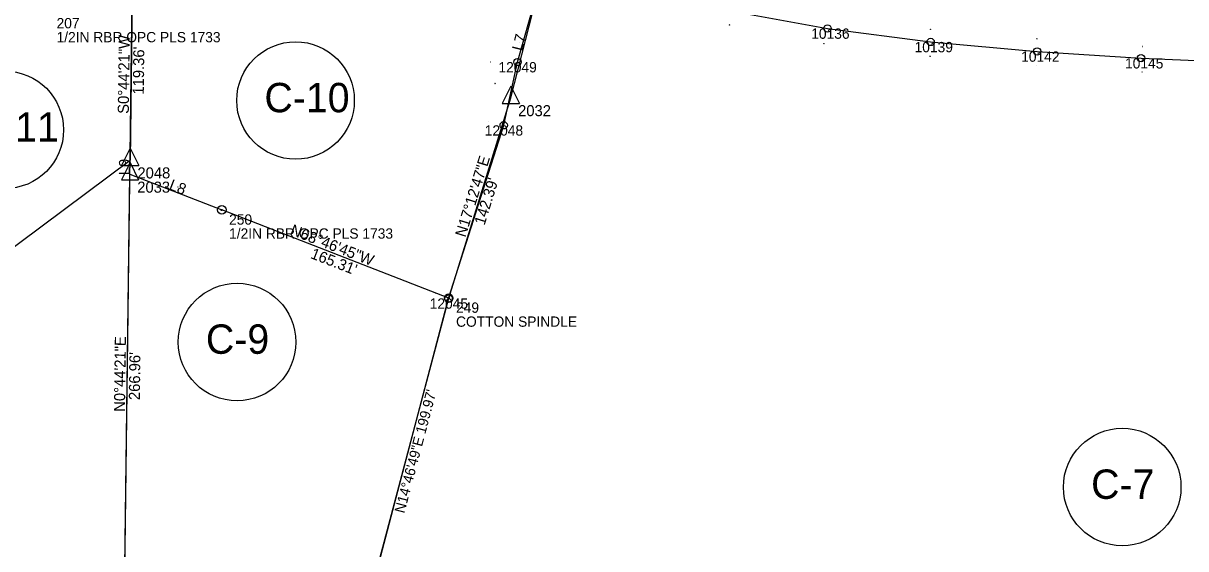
# Model space of a CAD drawing. Extents: x 1431802 to 1457777, y 1852108 to 1876350.
# Drawn here: x 1443655 to 1444444, y 1854558 to 1854914 of the extents above; entities that cross this region are included whole.
import ezdxf

# ---------------------------------------------------------------- set-up
doc = ezdxf.new("R2010")
doc.units = 0
for name, color, linetype in [('Default', 7, 'Continuous'), ('S_CAL_CORNER', 7, 'Continuous'), ('S_CAL_CORNER_ANNOT', 7, 'Continuous'), ('S_EXISTING_ALIGNMENT', 7, 'Continuous'), ('S_EXISTING_ALIGNMENT_ANNOT', 7, 'Continuous'), ('S_IRON_PIN', 7, 'Continuous'), ('S_IRON_PIN_ANNOT', 7, 'Continuous'), ('S_PROPERTY', 7, 'Continuous'), ('S_PROPERTY_ANNOT', 7, 'Continuous'), ('S_RDW_PT_SYM', 7, 'Continuous'), ('S_SECTION', 7, 'Continuous')]:
    doc.layers.add(name, color=color, linetype=linetype)

msp = doc.modelspace()

# ---------------------------------------------------------------- linework, layer by layer
at = {"layer": 'Default'}
for points in [[(1443991.62, 1854901.34), (1443991.57, 1854901.35), (1443991.62, 1854901.34), (1443991.61, 1854901.29), (1443991.62, 1854901.34), (1443991.67, 1854901.33), (1443991.62, 1854901.34), (1443991.63, 1854901.39)], [(1443723.6, 1854816.71), (1443723.55, 1854816.71), (1443723.6, 1854816.71), (1443723.6, 1854816.66), (1443723.6, 1854816.71), (1443723.65, 1854816.71), (1443723.6, 1854816.71), (1443723.6, 1854816.76)], [(1443759.83, 1854803.21), (1443759.85, 1854803.26), (1443759.83, 1854803.21), (1443759.78, 1854803.23), (1443759.83, 1854803.21), (1443759.81, 1854803.16), (1443759.83, 1854803.21), (1443759.88, 1854803.19)]]:
    msp.add_lwpolyline(points, dxfattribs=at)
at = {"layer": 'S_CAL_CORNER'}
for p, q in [((1443985.99, 1854871.76), (1443980.11, 1854859.94)), ((1443985.99, 1854871.76), (1443991.8, 1854859.94)), ((1443980.11, 1854859.94), (1443991.8, 1854859.94)), ((1443727.5, 1854829.48), (1443721.62, 1854817.67)), ((1443727.5, 1854829.48), (1443733.31, 1854817.67)), ((1443727.38, 1854819.8), (1443721.5, 1854807.99)), ((1443721.62, 1854817.67), (1443733.31, 1854817.67)), ((1443727.38, 1854819.8), (1443733.19, 1854807.99)), ((1443721.5, 1854807.99), (1443733.19, 1854807.99))]:
    msp.add_line(p, q, dxfattribs=at)
at = {"layer": 'S_EXISTING_ALIGNMENT'}
for p, q in [((1443990.44, 1854888.01), (1444004.54, 1854937.19)), ((1444136.32, 1854922.52), (1444201, 1854910.83)), ((1444201, 1854910.83), (1444271.02, 1854901.68)), ((1444271.02, 1854901.68), (1444343.36, 1854895.24)), ((1444343.36, 1854895.24), (1444413.89, 1854890.65)), ((1443981.13, 1854845.08), (1443990.44, 1854888.01)), ((1444413.89, 1854890.65), (1444489.02, 1854887.49)), ((1443943.72, 1854727.53), (1443981.13, 1854845.08)), ((1443892.71, 1854534.17), (1443943.72, 1854727.53))]:
    msp.add_line(p, q, dxfattribs=at)
for centre in [(1444201, 1854910.83), (1444271.02, 1854901.68), (1444343.36, 1854895.24), (1443990.44, 1854888.01), (1444413.89, 1854890.65), (1443981.13, 1854845.08), (1443943.72, 1854727.53)]:
    msp.add_circle(centre, 2.5, dxfattribs=at)
at = {"layer": 'S_IRON_PIN'}
for centre, radius in [((1443789.66, 1854787.6), 2.91), ((1443789.66, 1854787.6), 0.411), ((1443789.66, 1854787.6), 0.262), ((1443789.66, 1854787.6), 0.212), ((1443789.66, 1854787.6), 0.145), ((1443789.66, 1854787.6), 0.0822), ((1443789.66, 1854787.6), 0.0581), ((1443943.76, 1854727.77), 2.91), ((1443943.76, 1854727.77), 0.411), ((1443943.76, 1854727.77), 0.262), ((1443943.76, 1854727.77), 0.212), ((1443943.76, 1854727.77), 0.145), ((1443943.76, 1854727.77), 0.0822), ((1443943.76, 1854727.77), 0.0581)]:
    msp.add_circle(centre, radius, dxfattribs=at)
at = {"layer": 'S_PROPERTY'}
for p, q in [((1443728.95, 1854940.85), (1443727.41, 1854821.5)), ((1443985.9, 1854863.78), (1444004.6, 1854937.04)), ((1443943.76, 1854727.77), (1443985.9, 1854863.78)), ((1443347.68, 1854538.17), (1443727.41, 1854821.5)), ((1443727.29, 1854811.82), (1443727.41, 1854821.5)), ((1443723.84, 1854544.89), (1443727.29, 1854811.82)), ((1443727.29, 1854811.82), (1443789.66, 1854787.6)), ((1443943.76, 1854727.77), (1443789.66, 1854787.6)), ((1443789.66, 1854144.76), (1443943.76, 1854727.77))]:
    msp.add_line(p, q, dxfattribs=at)
for centre in [(1443839.79, 1854861.92), (1443642.38, 1854841.97), (1443800.04, 1854697.92), (1444401.12, 1854599.42)]:
    msp.add_circle(centre, 39.9, dxfattribs=at)
at = {"layer": 'S_RDW_PT_SYM'}
for points in [[(1444134.38, 1854913.21), (1444134.38, 1854913.26), (1444134.38, 1854913.21), (1444134.33, 1854913.21), (1444134.38, 1854913.21), (1444134.38, 1854913.16), (1444134.38, 1854913.21), (1444134.43, 1854913.21)], [(1444271.03, 1854910.26), (1444271.03, 1854910.31), (1444271.03, 1854910.26), (1444270.98, 1854910.26), (1444271.03, 1854910.26), (1444271.03, 1854910.21), (1444271.03, 1854910.26), (1444271.08, 1854910.26)], [(1444343.21, 1854903.87), (1444343.21, 1854903.92), (1444343.21, 1854903.87), (1444343.16, 1854903.87), (1444343.21, 1854903.87), (1444343.21, 1854903.82), (1444343.21, 1854903.87), (1444343.26, 1854903.87)], [(1444198.59, 1854900.72), (1444198.59, 1854900.77), (1444198.59, 1854900.72), (1444198.54, 1854900.72), (1444198.59, 1854900.72), (1444198.59, 1854900.67), (1444198.59, 1854900.72), (1444198.65, 1854900.72)], [(1444414.8, 1854898.63), (1444414.8, 1854898.68), (1444414.8, 1854898.63), (1444414.75, 1854898.63), (1444414.8, 1854898.63), (1444414.8, 1854898.58), (1444414.8, 1854898.63), (1444414.85, 1854898.63)], [(1443972.27, 1854888.19), (1443972.27, 1854888.24), (1443972.27, 1854888.19), (1443972.22, 1854888.19), (1443972.27, 1854888.19), (1443972.27, 1854888.14), (1443972.27, 1854888.19), (1443972.32, 1854888.19)], [(1444270.63, 1854891.92), (1444270.63, 1854891.97), (1444270.63, 1854891.92), (1444270.58, 1854891.92), (1444270.63, 1854891.92), (1444270.63, 1854891.87), (1444270.63, 1854891.92), (1444270.68, 1854891.92)], [(1444342.88, 1854885.9), (1444342.88, 1854885.95), (1444342.88, 1854885.9), (1444342.83, 1854885.9), (1444342.88, 1854885.9), (1444342.88, 1854885.85), (1444342.88, 1854885.9), (1444342.93, 1854885.9)], [(1444002.36, 1854885.42), (1444002.36, 1854885.47), (1444002.36, 1854885.42), (1444002.31, 1854885.42), (1444002.36, 1854885.42), (1444002.36, 1854885.37), (1444002.36, 1854885.42), (1444002.41, 1854885.42)], [(1444414.63, 1854881.32), (1444414.63, 1854881.37), (1444414.63, 1854881.32), (1444414.58, 1854881.32), (1444414.63, 1854881.32), (1444414.63, 1854881.27), (1444414.63, 1854881.32), (1444414.68, 1854881.32)], [(1443975.24, 1854873.57), (1443975.24, 1854873.62), (1443975.24, 1854873.57), (1443975.19, 1854873.57), (1443975.24, 1854873.57), (1443975.24, 1854873.52), (1443975.24, 1854873.57), (1443975.29, 1854873.57)], [(1443970.62, 1854847.9), (1443970.62, 1854847.95), (1443970.62, 1854847.9), (1443970.57, 1854847.9), (1443970.62, 1854847.9), (1443970.62, 1854847.85), (1443970.62, 1854847.9), (1443970.67, 1854847.9)], [(1443990.54, 1854841.84), (1443990.54, 1854841.89), (1443990.54, 1854841.84), (1443990.49, 1854841.84), (1443990.54, 1854841.84), (1443990.54, 1854841.79), (1443990.54, 1854841.84), (1443990.59, 1854841.84)], [(1443934.64, 1854730.62), (1443934.64, 1854730.67), (1443934.64, 1854730.62), (1443934.59, 1854730.62), (1443934.64, 1854730.62), (1443934.64, 1854730.57), (1443934.64, 1854730.62), (1443934.69, 1854730.62)], [(1443952.06, 1854724.65), (1443952.06, 1854724.7), (1443952.06, 1854724.65), (1443952.01, 1854724.65), (1443952.06, 1854724.65), (1443952.06, 1854724.6), (1443952.06, 1854724.65), (1443952.11, 1854724.65)]]:
    msp.add_lwpolyline(points, dxfattribs=at)
at = {"layer": 'S_SECTION'}
msp.add_line((1443711.83, 1853613.38), (1443728.95, 1854940.85), dxfattribs=at)

# ---------------------------------------------------------------- texts
at = {"layer": 'S_CAL_CORNER_ANNOT'}
for s, p in [('2032', (1443990.9, 1854851.28)), ('2048', (1443732.41, 1854809)), ('2033', (1443732.29, 1854799.32))]:
    msp.add_text(s, height=7.5, dxfattribs=at).set_placement(p)
at = {"layer": 'S_EXISTING_ALIGNMENT_ANNOT'}
for s, p in [('10136', (1444189.95, 1854903.83)), ('10139', (1444260.13, 1854894.68)), ('10142', (1444332.5, 1854888.24)), ('12049', (1443977.57, 1854881.01)), ('10145', (1444403.03, 1854883.65)), ('12048', (1443968.28, 1854838.08)), ('12045', (1443930.88, 1854720.53))]:
    msp.add_text(s, height=7, dxfattribs=at).set_placement(p)
msp.add_text('N14%%d46\'49"E 199.97\'', height=7, rotation=75.21977, dxfattribs=at).set_placement((1443913.65, 1854581.21))
at = {"layer": 'S_IRON_PIN_ANNOT'}
for s, p in [('207', (1443677.51, 1854910.93)), ('1/2IN RBR OPC PLS 1733', (1443677.51, 1854901.43)), ('250', (1443794.66, 1854777.6)), ('1/2IN RBR OPC PLS 1733', (1443794.66, 1854768.1)), ('249', (1443948.76, 1854717.77)), ('COTTON SPINDLE', (1443948.76, 1854708.27))]:
    msp.add_text(s, height=7, dxfattribs=at).set_placement(p)
at = {"layer": 'S_PROPERTY'}
for s, p in [('C-10', (1443818.65, 1854853.92)), ('C-11', (1443621.24, 1854833.96)), ('C-9', (1443778.91, 1854689.92)), ('C-7', (1444379.99, 1854591.41))]:
    msp.add_text(s, height=19.95, dxfattribs=at).set_placement(p)
at = {"layer": 'S_PROPERTY_ANNOT'}
for s, rotation, p in [('S0%%d44\'21"W', 89.26094, (1443726.56, 1854852.85)), ('L7', 75.67949, (1443993.89, 1854895.09)), ("119.36'", 89.26094, (1443736.73, 1854865.89)), ('N17%%d12\'47"E', 72.78692, (1443955.11, 1854768.62)), ('L9', 89.26094, (1443727.28, 1854811.14)), ('L8', 338.77912, (1443753.35, 1854801.7)), ("142.39'", 72.78692, (1443968.12, 1854776.83)), ('N68%%d46\'45"W', 338.77912, (1443835.56, 1854771.12)), ("165.31'", 338.77912, (1443849.4, 1854755.02)), ('N0%%d44\'21"E', 89.26094, (1443723.95, 1854650.5)), ("266.96'", 89.26094, (1443734.06, 1854658.46))]:
    msp.add_text(s, height=7.5, rotation=rotation, dxfattribs=at).set_placement(p)

doc.saveas('drawing.dxf')
